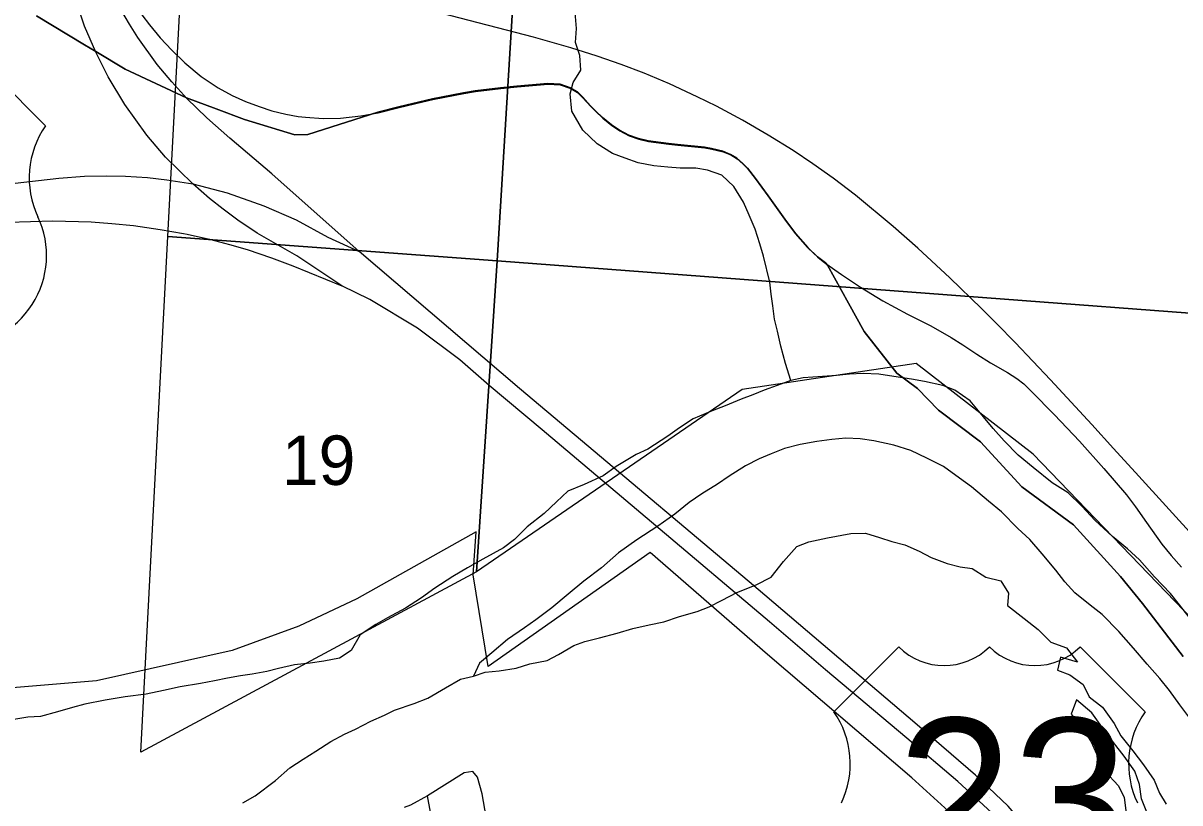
# Model space of a CAD drawing. Extents: x 0 to 34, y 0 to 22.
# Drawn here: x 6 to 6.981, y 14.951 to 15.611 of the extents above; entities that cross this region are included whole.
import ezdxf

# ---------------------------------------------------------------- set-up
doc = ezdxf.new("R2010")
doc.units = 0
for name, color, linetype in [('GM_X_City_Street', 7, 'Continuous'), ('GM_X_Corporation', 7, 'Continuous'), ('GM_X_County_Road', 7, 'Continuous'), ('GM_X_Major_River', 7, 'Continuous'), ('GM_X_Minor_River', 7, 'Continuous'), ('GM_X_Rail_Line', 7, 'Continuous'), ('GM_X_Section_Text', 7, 'Continuous'), ('GM_X_US_Location', 7, 'Continuous'), ('GM_X_US_Route', 7, 'Continuous'), ('GM_X_US_Shield', 7, 'Continuous'), ('SH_Data', 7, 'Continuous')]:
    doc.layers.add(name, color=color, linetype=linetype)

msp = doc.modelspace()

# ---------------------------------------------------------------- linework, layer by layer
at = {"layer": 'GM_X_City_Street'}
for points in [[(6.42539, 14.77539), (6.40249, 14.88381), (6.38951, 14.95825), (6.38532, 14.97238), (6.3815, 14.97734), (6.37425, 14.9762), (6.34296, 14.95672), (6.32854, 14.94867), (6.32322, 14.94657)], [(6.37769, 14.76775), (6.35798, 14.87498), (6.34296, 14.95672)]]:
    msp.add_lwpolyline(points, dxfattribs=at)
at = {"layer": 'GM_X_Corporation'}
for points in [[(5.52353, 16.47441), (6.46299, 16.40893), (6.40215, 15.40998), (6.12308, 15.43064), (6.14643, 15.87674), (5.48379, 15.92801)], [(6.46299, 16.40893), (7.49635, 16.3324), (7.43399, 15.33194), (6.40215, 15.40998)], [(6.12308, 15.43064), (6.40215, 15.40998), (6.3846, 15.14643), (6.10015, 14.99363)], [(6.40215, 15.40998), (7.43399, 15.33194), (7.37729, 14.33069), (7.2777, 14.33798), (7.28983, 14.65573), (7.18882, 14.8361), (7.05907, 15.03562), (6.8563, 15.24606), (6.75704, 15.32306), (6.60959, 15.30103), (6.3846, 15.14643)]]:
    msp.add_lwpolyline(points, close=True, dxfattribs=at)
for points in [[(6.98338, 15.0746), (6.94893, 15.11966), (6.93019, 15.14258), (6.89044, 15.18616), (6.8468, 15.21839), (6.81155, 15.25663), (6.7762, 15.28348), (6.75819, 15.30184), (6.74089, 15.31488), (6.71317, 15.35002), (6.69979, 15.37415), (6.68216, 15.40624), (6.68047, 15.40816), (6.67364, 15.41349), (6.66539, 15.42129), (6.655, 15.43313), (6.64592, 15.44515), (6.63169, 15.46491), (6.62096, 15.47974), (6.61426, 15.48837), (6.61008, 15.49282), (6.60529, 15.49689), (6.59987, 15.50021), (6.59331, 15.50293), (6.58372, 15.5052), (6.57774, 15.50621), (6.55494, 15.50862), (6.54729, 15.50942), (6.53013, 15.51156), (6.52185, 15.5135), (6.51363, 15.51654), (6.50576, 15.52071), (6.49893, 15.5252), (6.49133, 15.53148), (6.48536, 15.53704), (6.4813, 15.54134), (6.47462, 15.54871), (6.47007, 15.55309), (6.46427, 15.55665), (6.4554, 15.55955), (6.44498, 15.56015), (6.41887, 15.55796), (6.40499, 15.55665), (6.38349, 15.55396), (6.37351, 15.55226), (6.34736, 15.5472), (6.31883, 15.54046), (6.30095, 15.53604), (6.24171, 15.51712), (6.23051, 15.51676), (6.18806, 15.5296), (6.16392, 15.5389), (6.13889, 15.54817), (6.08681, 15.57229), (6.06191, 15.58723), (6.05239, 15.59294), (6.01173, 15.61756)], [(6.01173, 15.61756), (6.05239, 15.59294), (6.06191, 15.58723), (6.08681, 15.57229), (6.13889, 15.54817), (6.16392, 15.5389), (6.18806, 15.5296), (6.23051, 15.51676), (6.24171, 15.51712), (6.30095, 15.53604), (6.31883, 15.54046), (6.34736, 15.5472), (6.37351, 15.55226), (6.38349, 15.55396), (6.40499, 15.55665), (6.41887, 15.55796), (6.44498, 15.56015), (6.4554, 15.55955), (6.46427, 15.55665), (6.47007, 15.55309), (6.47462, 15.54871), (6.4813, 15.54134), (6.48536, 15.53704), (6.49133, 15.53148), (6.49893, 15.5252), (6.50576, 15.52071), (6.51363, 15.51654), (6.52185, 15.5135), (6.53013, 15.51156), (6.54729, 15.50942), (6.55494, 15.50862), (6.57774, 15.50621), (6.58372, 15.5052), (6.59331, 15.50293), (6.59987, 15.50021), (6.60529, 15.49689), (6.61008, 15.49282), (6.61426, 15.48837), (6.62096, 15.47974), (6.63169, 15.46491), (6.64592, 15.44515), (6.655, 15.43313), (6.66539, 15.42129), (6.67364, 15.41349), (6.68047, 15.40816), (6.68216, 15.40624), (6.69979, 15.37415), (6.71317, 15.35002), (6.74089, 15.31488), (6.75819, 15.30184), (6.7762, 15.28348), (6.81155, 15.25663), (6.8468, 15.21839), (6.89044, 15.18616), (6.93019, 15.14258), (6.94893, 15.11966), (6.98338, 15.0746)], [(6.98195, 14.31913), (6.95811, 14.4456), (6.93585, 14.53679), (6.91219, 14.61154), (6.89881, 14.67185), (6.88072, 14.75986), (6.86772, 14.82824), (6.86075, 14.85218), (6.84771, 14.87429), (6.82975, 14.89643), (6.79377, 14.93504), (6.75361, 14.97177), (6.6312, 15.07632), (6.53171, 15.16286), (6.3946, 15.06614), (6.38169, 15.144), (6.38429, 15.18039), (6.28311, 15.12357), (6.23409, 15.10046), (6.17752, 15.07969), (6.06263, 15.0541), (5.93349, 15.04341)]]:
    msp.add_lwpolyline(points, dxfattribs=at)
at = {"layer": 'GM_X_County_Road'}
for points in [[(6.10091, 15.61854), (6.10737, 15.60997), (6.11648, 15.59889), (6.12628, 15.58836), (6.1375, 15.5777), (6.15135, 15.5663), (6.16581, 15.55657), (6.17744, 15.55015), (6.18314, 15.54759)], [(6.33902, 15.54465), (6.34758, 15.54668), (6.37373, 15.55173), (6.38371, 15.55343), (6.40521, 15.55612), (6.41909, 15.55743), (6.44519, 15.55962), (6.45561, 15.55902), (6.46449, 15.55612), (6.47029, 15.55257), (6.47484, 15.54818), (6.48152, 15.54081), (6.48558, 15.53651), (6.49155, 15.53096), (6.49915, 15.52467), (6.50598, 15.52019), (6.51385, 15.51601), (6.52207, 15.51297), (6.53035, 15.51104), (6.54751, 15.5089), (6.55516, 15.50809), (6.57796, 15.50569), (6.58394, 15.50467), (6.59353, 15.50241), (6.60009, 15.49968), (6.6055, 15.49637), (6.6103, 15.49229), (6.61448, 15.48784), (6.62118, 15.47921), (6.63191, 15.46439), (6.64614, 15.44462), (6.65521, 15.4326), (6.66561, 15.42076), (6.67386, 15.41296), (6.67841, 15.40941)], [(6.18314, 15.54759), (6.18884, 15.54504), (6.2003, 15.54066), (6.2111, 15.5372), (6.22308, 15.5342), (6.23333, 15.53234), (6.23972, 15.53165), (6.2546, 15.53058), (6.26941, 15.53089), (6.28667, 15.53275), (6.30117, 15.53551), (6.31905, 15.53993), (6.33902, 15.54465)], [(6.67841, 15.40941), (6.68069, 15.40763), (6.69381, 15.39833), (6.71003, 15.38762), (6.72902, 15.37606), (6.7498, 15.36474), (6.76951, 15.35479), (6.78695, 15.34509), (6.79672, 15.33881), (6.80853, 15.33078), (6.82016, 15.32352), (6.83462, 15.31527), (6.84235, 15.31033), (6.84836, 15.30584), (6.85475, 15.29963), (6.87442, 15.27957), (6.89565, 15.2571), (6.91619, 15.23411), (6.93549, 15.21157), (6.94312, 15.20159), (6.95241, 15.1883), (6.96539, 15.1699), (6.97312, 15.16023), (6.98203, 15.1504)]]:
    msp.add_lwpolyline(points, dxfattribs=at)
at = {"layer": 'GM_X_Major_River'}
for points in [[(6.95917, 15.14211), (6.94633, 15.15654), (6.93613, 15.16603), (6.92367, 15.17628), (6.90893, 15.18995), (6.8976, 15.2021), (6.8859, 15.21349), (6.87229, 15.22185), (6.85642, 15.23476), (6.84357, 15.24539), (6.83187, 15.25754), (6.82242, 15.26779), (6.81412, 15.27766), (6.8028, 15.29132), (6.78995, 15.30044), (6.77974, 15.30424), (6.76422, 15.30767), (6.75325, 15.30959), (6.73812, 15.31188), (6.72563, 15.31379), (6.71238, 15.31457), (6.70065, 15.31383), (6.68967, 15.3127), (6.67793, 15.31196), (6.66128, 15.31085), (6.65105, 15.30858), (6.63931, 15.30443), (6.62832, 15.30028), (6.61885, 15.29649), (6.609, 15.29272), (6.59536, 15.28705), (6.58437, 15.28289), (6.56808, 15.27609), (6.55671, 15.26852), (6.54685, 15.26133), (6.52979, 15.25036), (6.51994, 15.24582), (6.50288, 15.23561), (6.49189, 15.22766), (6.47597, 15.22048), (6.46196, 15.21481), (6.45247, 15.20573), (6.44185, 15.19588), (6.42744, 15.18453), (6.41682, 15.17393), (6.40734, 15.16674), (6.38991, 15.15728), (6.37702, 15.14971), (6.36452, 15.14253), (6.34935, 15.13269), (6.33798, 15.12437), (6.32433, 15.11566), (6.30917, 15.10735), (6.29932, 15.10167), (6.28605, 15.09297), (6.27845, 15.07971), (6.26859, 15.07328), (6.25534, 15.07064), (6.2436, 15.06914), (6.23035, 15.06764), (6.21672, 15.06463), (6.20687, 15.06199), (6.19438, 15.05973), (6.18453, 15.05823), (6.17355, 15.05635), (6.16257, 15.05409), (6.15083, 15.05183), (6.13341, 15.04882), (6.1194, 15.04581), (6.10463, 15.04279), (6.08684, 15.04054), (6.0698, 15.03753), (6.05275, 15.03414), (6.04215, 15.0315), (6.02965, 15.02773), (6.01526, 15.02396), (6.00428, 15.02321), (5.99254, 15.02134)], [(6.98919, 15.02227), (6.98051, 15.03366), (6.97183, 15.0458), (6.96352, 15.05605), (6.95295, 15.06819), (6.94125, 15.08186), (6.92879, 15.0959), (6.91481, 15.11033), (6.90461, 15.1183), (6.89176, 15.12856), (6.88308, 15.13804), (6.87553, 15.14791), (6.86383, 15.16158), (6.85363, 15.17372), (6.84343, 15.18321), (6.82946, 15.19726), (6.8185, 15.20637), (6.80415, 15.21853), (6.79394, 15.22574), (6.78034, 15.23562), (6.76635, 15.24284), (6.75274, 15.2493), (6.73836, 15.25387), (6.72134, 15.25731), (6.70961, 15.25922), (6.69749, 15.25961), (6.68576, 15.25849), (6.67289, 15.25699), (6.65888, 15.25436), (6.64562, 15.25096), (6.63425, 15.24643), (6.62403, 15.24227), (6.61266, 15.23622), (6.59863, 15.22752), (6.58877, 15.22071), (6.57551, 15.21238), (6.56489, 15.20519), (6.55276, 15.19535), (6.53835, 15.18514), (6.52053, 15.17341), (6.50499, 15.16243), (6.49058, 15.14994), (6.47541, 15.13859), (6.46214, 15.12761), (6.44849, 15.11588), (6.43484, 15.10566), (6.42536, 15.09885), (6.41095, 15.08901), (6.39768, 15.07765), (6.38706, 15.06895), (6.38215, 15.0579)], [(6.38215, 15.0579), (6.39196, 15.06136), (6.4037, 15.06248), (6.41809, 15.06473), (6.42983, 15.06851), (6.4446, 15.07114), (6.45407, 15.07644), (6.46696, 15.084), (6.47643, 15.0874), (6.48893, 15.09042), (6.5037, 15.09457), (6.51696, 15.09834), (6.53097, 15.10136), (6.54347, 15.10399), (6.55673, 15.10853), (6.5715, 15.11268), (6.58173, 15.11683), (6.59272, 15.12251), (6.60522, 15.12893), (6.62151, 15.13536), (6.6344, 15.14179), (6.64465, 15.15504), (6.65603, 15.16792), (6.66626, 15.1717), (6.68217, 15.17509), (6.70186, 15.17885), (6.71435, 15.17921), (6.72607, 15.17541), (6.73667, 15.17198), (6.74764, 15.16931), (6.75974, 15.16399), (6.76995, 15.15867), (6.78356, 15.15334), (6.79453, 15.15067), (6.80475, 15.14914), (6.81609, 15.14192), (6.82895, 15.13887), (6.83536, 15.12825), (6.83458, 15.11801), (6.84856, 15.107), (6.86066, 15.09751), (6.87123, 15.08688), (6.88447, 15.08193), (6.8939, 15.06979), (6.87953, 15.07398), (6.87686, 15.06299), (6.88745, 15.05918), (6.89878, 15.05082), (6.90368, 15.04058), (6.91502, 15.03185), (6.92483, 15.01781), (6.93048, 15.00756), (6.94067, 14.99466), (6.94973, 14.98289), (6.95879, 14.96999), (6.96331, 14.95899), (6.96897, 14.94951)], [(6.99164, 15.10416), (6.98032, 15.11858), (6.97277, 15.12807), (6.95917, 15.14211)], [(6.3151, 15.02926), (6.33172, 15.0349), (6.34346, 15.03943), (6.35825, 15.04813), (6.37113, 15.05532), (6.38215, 15.0579)], [(6.95267, 14.9427), (6.94816, 14.95408), (6.94629, 14.96622), (6.94253, 14.9776), (6.93347, 14.99012), (6.92442, 15.00188), (6.9146, 15.01517), (6.90592, 15.02693), (6.89308, 15.03794), (6.88851, 15.02581), (6.8987, 15.01291), (6.90549, 15.00229), (6.91114, 14.98977), (6.91717, 14.97763), (6.9285, 14.9651), (6.9334, 14.95524), (6.93526, 14.94197)], [(6.18656, 14.95055), (6.19717, 14.9566), (6.21423, 14.96947), (6.22637, 14.98045), (6.23774, 14.98763), (6.24836, 14.99444), (6.26124, 15.00277), (6.27261, 15.00882), (6.28209, 15.01298), (6.29497, 15.01978), (6.30672, 15.02507), (6.3151, 15.02926)]]:
    msp.add_lwpolyline(points, dxfattribs=at)
at = {"layer": 'GM_X_Minor_River'}
msp.add_lwpolyline([(6.65105, 15.30858), (6.64654, 15.323), (6.64241, 15.33779), (6.63979, 15.35031), (6.63716, 15.36055), (6.63567, 15.37192), (6.63418, 15.38178), (6.63307, 15.39202), (6.62782, 15.41402), (6.62481, 15.42426), (6.62068, 15.43678), (6.61578, 15.44854), (6.61089, 15.45954), (6.60259, 15.47282), (6.59239, 15.48269), (6.58029, 15.48688), (6.57046, 15.48841), (6.55721, 15.48843), (6.54661, 15.4892), (6.53488, 15.49035), (6.52164, 15.49303), (6.51067, 15.49683), (6.4997, 15.50102), (6.48685, 15.509), (6.47476, 15.52077), (6.46534, 15.5367), (6.46386, 15.55149), (6.46653, 15.56097), (6.47299, 15.57158), (6.47226, 15.58409), (6.4685, 15.59509), (6.46928, 15.60684), (6.46818, 15.62049)], dxfattribs=at)
at = {"layer": 'GM_X_Rail_Line'}
msp.add_lwpolyline([(7.07163, 15.08938), (6.94574, 15.22752), (6.92443, 15.25091), (6.90591, 15.27123), (6.87104, 15.30917), (6.84105, 15.34072), (6.82552, 15.35668), (6.81242, 15.36969), (6.78578, 15.39552), (6.7585, 15.42081), (6.73773, 15.43905), (6.70584, 15.4657), (6.68688, 15.47988), (6.66962, 15.49225), (6.65282, 15.50345), (6.63187, 15.51646), (6.6101, 15.5292), (6.58806, 15.54103), (6.57171, 15.54898), (6.54823, 15.55982), (6.52664, 15.56894), (6.50722, 15.57644), (6.48672, 15.58348), (6.46441, 15.59035), (6.43298, 15.59938), (6.35548, 15.61952)], dxfattribs=at)
at = {"layer": 'GM_X_US_Route'}
for points in [[(6.27061, 15.38867), (6.23221, 15.41414), (6.19878, 15.43335), (6.18236, 15.44451), (6.1698, 15.45369), (6.15837, 15.46266), (6.1443, 15.4752), (6.12114, 15.49784), (6.10535, 15.51652), (6.08666, 15.54258), (6.07245, 15.566), (6.06213, 15.5867), (6.05245, 15.60891), (6.04508, 15.63049)], [(6.2853, 15.41785), (6.21113, 15.48368), (6.17548, 15.51383), (6.15614, 15.53102), (6.13911, 15.54764), (6.12632, 15.56161), (6.11389, 15.57632), (6.09769, 15.59923), (6.09042, 15.61042), (6.08322, 15.62291)], [(5.99368, 15.47575), (6.03057, 15.4801), (6.05239, 15.48162), (6.07095, 15.482), (6.08726, 15.48175), (6.10569, 15.48044), (6.12212, 15.47865), (6.1443, 15.4752), (6.17318, 15.46759), (6.2045, 15.45654), (6.23188, 15.44469), (6.25856, 15.43012), (6.2853, 15.41785)], [(5.42944, 15.3891), (5.43444, 15.38975), (5.49805, 15.39826), (5.57968, 15.4089), (5.68208, 15.42269), (5.72075, 15.42732), (5.76241, 15.43151), (5.81193, 15.43508), (5.86343, 15.4373), (5.9267, 15.44029), (5.98776, 15.44261), (6.02566, 15.44376), (6.05795, 15.44289), (6.07562, 15.44174), (6.09385, 15.43991), (6.11642, 15.43663), (6.13616, 15.43304)], [(6.13616, 15.43304), (6.13928, 15.43248), (6.15828, 15.42843), (6.17526, 15.4239), (6.1903, 15.41946), (6.21094, 15.41251), (6.22888, 15.40567), (6.27061, 15.38867)], [(6.4673, 15.26274), (6.4209, 15.30182), (6.2853, 15.41785)], [(7.0457, 14.1), (7.03591, 14.14142), (6.95231, 14.57481), (6.93097, 14.6844), (6.91809, 14.74879), (6.91257, 14.7751), (6.90743, 14.79244), (6.89703, 14.82324), (6.89019, 14.84038), (6.8794, 14.86091), (6.86598, 14.88512), (6.84703, 14.91144), (6.82492, 14.93881), (6.79255, 14.96882), (6.74912, 15.0054), (6.68043, 15.0633), (6.63279, 15.1041), (6.44013, 15.26675), (6.39539, 15.30439), (6.37038, 15.32597), (6.33459, 15.35282), (6.29406, 15.37729), (6.27061, 15.38867)], [(6.65732, 15.10243), (6.61566, 15.13784), (6.4673, 15.26274)], [(6.92044, 14.80017), (6.91044, 14.82859), (6.90123, 14.85123), (6.89201, 14.86991), (6.88096, 14.88939), (6.86806, 14.9086), (6.85096, 14.92939), (6.83516, 14.94782), (6.80753, 14.97414), (6.75805, 15.01678), (6.65732, 15.10243)]]:
    msp.add_lwpolyline(points, dxfattribs=at)
at = {"layer": 'GM_X_US_Shield'}
for p, q in [((6.01943, 15.52446), (5.9645, 15.57939)), ((6.74236, 15.08273), (6.68742, 15.0278)), ((6.9511, 15.0278), (6.89616, 15.08273))]:
    msp.add_line(p, q, dxfattribs=at)
for centre, radius, start, end in [((6.08243, 15.48035), 0.0769, 144.99907, 205.45288), ((5.94338, 15.41459), 0.0769, 269.36174, 25.16808), ((6.78081, 15.12196), 0.05493, 225.573, 314.427), ((6.85771, 15.12196), 0.05493, 225.573, 314.427), ((6.62443, 14.98368), 0.0769, 334.54712, 35.00093), ((7.01409, 14.98368), 0.0769, 144.99907, 205.45288)]:
    msp.add_arc(centre, radius, start, end, dxfattribs=at)
at = {"layer": 'SH_Data'}
for p, q in [((6.01943, 15.52446), (5.9645, 15.57939)), ((6.74236, 15.08273), (6.68742, 15.0278)), ((6.9511, 15.0278), (6.89616, 15.08273))]:
    msp.add_line(p, q, dxfattribs=at)
for centre, radius, start, end in [((6.08243, 15.48035), 0.0769, 144.99907, 205.45288), ((5.94338, 15.41459), 0.0769, 269.36174, 25.16808), ((6.78081, 15.12196), 0.05493, 225.573, 314.427), ((6.85771, 15.12196), 0.05493, 225.573, 314.427), ((6.62443, 14.98368), 0.0769, 334.54712, 35.00093), ((7.01409, 14.98368), 0.0769, 144.99907, 205.45288)]:
    msp.add_arc(centre, radius, start, end, dxfattribs=at)

# ---------------------------------------------------------------- texts
at = {"layer": 'GM_X_Section_Text'}
msp.add_text('19', height=0.041856, rotation=0.00001, dxfattribs=at).set_placement((6.21968, 15.22008))
at = {"layer": 'GM_X_US_Location'}
for s, p in [('0', (6.81919, 14.95535)), ('/', (6.81921, 14.95535))]:
    msp.add_text(s, height=0.000189, dxfattribs=at).set_placement(p)
at = {"layer": 'GM_X_US_Shield'}
msp.add_text('23', height=0.131836, dxfattribs=at).set_placement((6.74098, 14.89047))
at = {"layer": 'SH_Data'}
msp.add_text('23', height=0.131836, dxfattribs=at).set_placement((6.74098, 14.89047))

doc.saveas('drawing.dxf')
